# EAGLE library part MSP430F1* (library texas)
MIXED SIGNAL MICROCONTROLLER Family Members Include: - MSP430F133: 8KB+256B Flash Memory, 256B RAM - MSP430F135: 16KB+256B Flash Memory, 512B RAM - MSP430F147, MSP430F1471: 32KB+256B Flash Memory, 1KB RAM - MSP430F148, MSP430F1481: 48KB+256B Flash Memory, 2KB RAM - MSP430F149, MSP430F1491: 60KB+256B Flash Memory, 2KB RAM
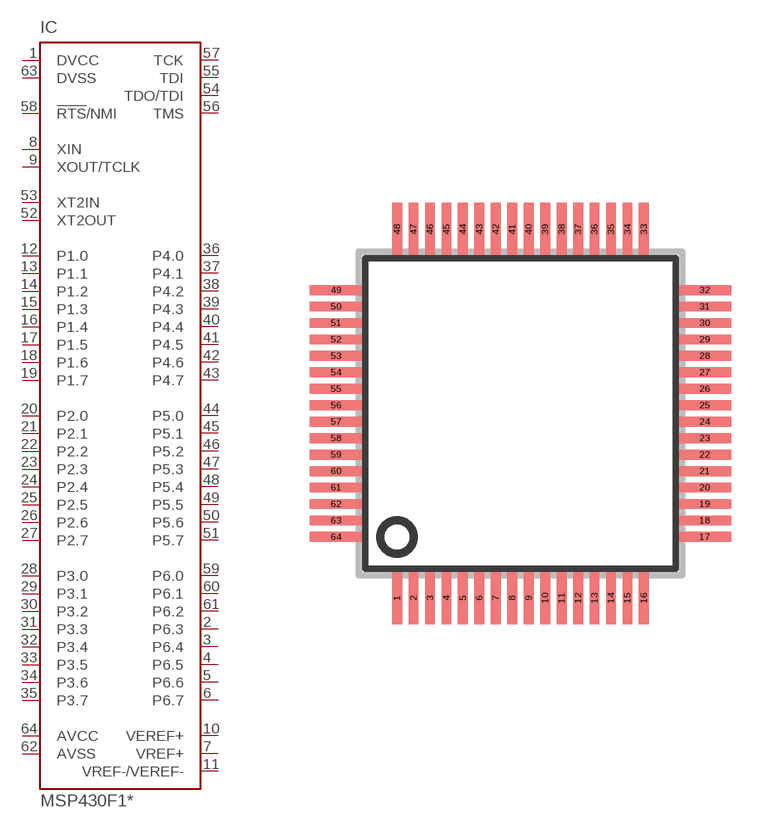
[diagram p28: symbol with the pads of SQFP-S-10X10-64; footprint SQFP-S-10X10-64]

Designator prefix IC

## MSP430F133 (MF: TEXAS INSTRUMENTS; MPN: MSP430F133IPM; OC_FARNELL: 1471268; OC_NEWARK: 75C4034), MSP430F135 (MF: TEXAS INSTRUMENTS; MPN: MSP430F135IPM; OC_FARNELL: 1106050; OC_NEWARK: 75C4036), MSP430F147 (MPN: MSP430F1471IPM; OC_FARNELL: 1649389; OC_NEWARK: 95M6746), MSP430F148 (MPN: MSP430F1481IPM; OC_FARNELL: 1649391; OC_NEWARK: 95M6750), MSP430F149 (MPN: MSP430F1491IRTDT; OC_FARNELL: 1537170; OC_NEWARK: 95M6752), MSP430F1471 (MPN: MSP430F1471IRTDT; OC_FARNELL: 1537163; OC_NEWARK: 95M6747), MSP430F1481 (MPN: MSP430F1481IPM; OC_FARNELL: 1649391; OC_NEWARK: 95M6750), MSP430F1491 (MF: TEXAS INSTRUMENT CONNECTORS; MPN: MSP430F1491IPM; OC_FARNELL: 1537169; OC_NEWARK: 34K8186)  [SQFP-S-10X10-64]
1  DVCC  pwr
2  P6.3
3  P6.4
4  P6.5
5  P6.6
6  P6.7
7  VREF+  out
8  XIN  in
9  XOUT/TCLK
10  VEREF+  in
11  VREF-/VEREF-
12  P1.0
13  P1.1
14  P1.2
15  P1.3
16  P1.4
17  P1.5
18  P1.6
19  P1.7
20  P2.0
21  P2.1
22  P2.2
23  P2.3
24  P2.4
25  P2.5
26  P2.6
27  P2.7
28  P3.0
29  P3.1
30  P3.2
31  P3.3
32  P3.4
33  P3.5
34  P3.6
35  P3.7
36  P4.0
37  P4.1
38  P4.2
39  P4.3
40  P4.4
41  P4.5
42  P4.6
43  P4.7
44  P5.0
45  P5.1
46  P5.2
47  P5.3
48  P5.4
49  P5.5
50  P5.6
51  P5.7
52  XT2OUT  out
53  XT2IN  in
54  TDO/TDI
55  TDI  in
56  TMS  in
57  TCK  in
58  !RTS!/NMI  in
59  P6.0
60  P6.1
61  P6.2
62  AVSS  pwr
63  DVSS  pwr
64  AVCC  pwr

## Footprint SQFP-S-10X10-64 (pad centres in mm)
QFP64 shrink quad flat pack, square
smd 0.3 x 1.6: 1 -3.75,-5.6; 2 -3.25,-5.6; 3 -2.75,-5.6; 4 -2.25,-5.6; 5 -1.75,-5.6; 6 -1.25,-5.6; 7 -0.75,-5.6; 8 -0.25,-5.6; 9 0.25,-5.6; 10 0.75,-5.6; 11 1.25,-5.6; 12 1.75,-5.6; 13 2.25,-5.6; 14 2.75,-5.6; 15 3.25,-5.6; 16 3.75,-5.6; 33 3.75,5.6; 34 3.25,5.6; 35 2.75,5.6; 36 2.25,5.6; 37 1.75,5.6; 38 1.25,5.6; 39 0.75,5.6; 40 0.25,5.6; 41 -0.25,5.6; 42 -0.75,5.6; 43 -1.25,5.6; 44 -1.75,5.6; 45 -2.25,5.6; 46 -2.75,5.6; 47 -3.25,5.6; 48 -3.75,5.6
smd 1.6 x 0.3: 17 5.6,-3.75; 18 5.6,-3.25; 19 5.6,-2.75; 20 5.6,-2.25; 21 5.6,-1.75; 22 5.6,-1.25; 23 5.6,-0.75; 24 5.6,-0.25; 25 5.6,0.25; 26 5.6,0.75; 27 5.6,1.25; 28 5.6,1.75; 29 5.6,2.25; 30 5.6,2.75; 31 5.6,3.25; 32 5.6,3.75; 49 -5.6,3.75; 50 -5.6,3.25; 51 -5.6,2.75; 52 -5.6,2.25; 53 -5.6,1.75; 54 -5.6,1.25; 55 -5.6,0.75; 56 -5.6,0.25; 57 -5.6,-0.25; 58 -5.6,-0.75; 59 -5.6,-1.25; 60 -5.6,-1.75; 61 -5.6,-2.25; 62 -5.6,-2.75; 63 -5.6,-3.25; 64 -5.6,-3.75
